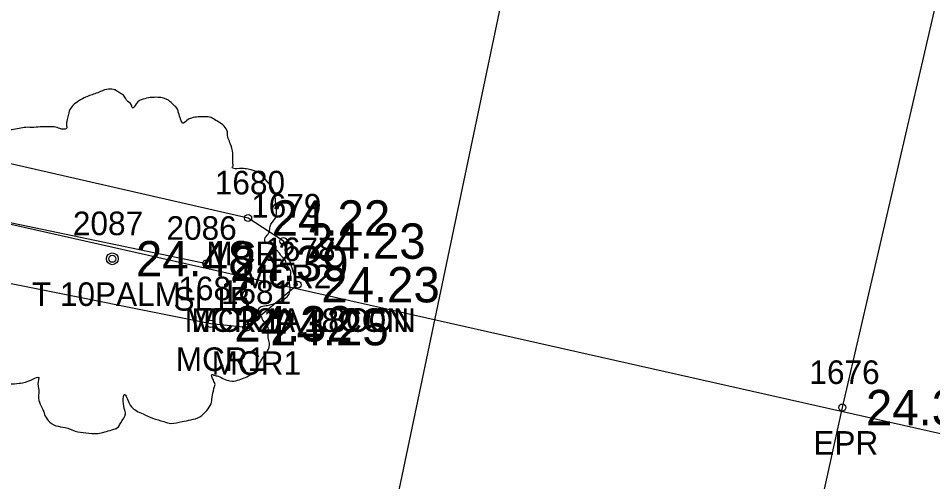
# Model space of a CAD drawing. Extents: x 2654414 to 2656963, y 761776 to 764965.
# Drawn here: x 2655431.68 to 2655470.4, y 762194.36 to 762214.01 of the extents above; entities that cross this region are included whole.
import ezdxf

# ---------------------------------------------------------------- set-up
doc = ezdxf.new("R2010")
doc.units = 0
for name, color, linetype in [('RD_EX_Conc', 7, 'Continuous'), ('RD_EX_Conc_txCode', 7, 'Continuous'), ('RD_EX_DR_Pipe', 7, 'Continuous'), ('RD_EX_Road', 7, 'Continuous'), ('RD_EX_Road_txCode', 7, 'Continuous'), ('RD_EX_TX_Conc_ELEV', 7, 'Continuous'), ('RD_EX_TX_Road_ELEV', 7, 'Continuous'), ('RD_EX_TX_VEG_ELEV', 7, 'Continuous'), ('RD_EX_VEG', 7, 'Continuous'), ('RD_EX_VEG_txCode', 7, 'Continuous'), ('RD_HC_Cl', 7, 'Continuous'), ('RD_SMD_Locator', 7, 'Continuous')]:
    doc.layers.add(name, color=color, linetype=linetype)

msp = doc.modelspace()

# ---------------------------------------------------------------- linework, layer by layer
at = {"layer": 'RD_EX_Conc'}
for points in [[(2655443.509, 762202.713), (2655441.344, 762200.892), (2655439.828, 762201.054), (2655414.24, 762206.177), (2655412.261, 762207.947), (2655412.231, 762209.572), (2655413.306, 762211.312), (2655415.917, 762211.372)], [(2655443.509, 762202.713), (2655442.909, 762204.561), (2655441.41, 762205.54), (2655415.917, 762211.372)]]:
    msp.add_lwpolyline(points, dxfattribs=at)
at = {"layer": 'RD_EX_DR_Pipe'}
msp.add_line((2655454.649, 762226.686), (2655442.695, 762169.731), dxfattribs=at)
at = {"layer": 'RD_EX_Road'}
msp.add_lwpolyline([(2655700.994, 763232.279), (2655693.552, 763198.573), (2655671.649, 763102.037), (2655649.038, 763001.061), (2655627.271, 762906.233), (2655604.996, 762809.365), (2655598.992, 762783.09), (2655583.655, 762714.137), (2655561.97, 762618.323), (2655556.356, 762593.843), (2655548.114, 762557.141), (2655540.102, 762522.478), (2655518.03, 762425.04), (2655496.479, 762329.558), (2655475.552, 762236.625), (2655473.199, 762226.142), (2655466.574, 762197.504), (2655460.058, 762168.164), (2655454.261, 762143.776), (2655432.5, 762049.878), (2655410.7, 761955.515), (2655388.166, 761858.426), (2655373.501, 761793.951)], dxfattribs=at)
at = {"layer": 'RD_EX_VEG'}
msp.add_line((2655415.141, 762208.748), (2655439.646, 762203.615), dxfattribs=at)
for centre, radius in [((2655435.66, 762203.812), 0.25), ((2655435.647, 762203.793), 0.0001)]:
    msp.add_circle(centre, radius, dxfattribs=at)
for points in [[(2655435.792, 762210.979), (2655435.492, 762211.004), (2655435.167, 762210.904), (2655434.917, 762210.804), (2655434.692, 762210.729), (2655434.468, 762210.629), (2655434.168, 762210.454), (2655433.943, 762210.254), (2655433.818, 762210.004), (2655433.768, 762209.779), (2655433.718, 762209.505), (2655433.718, 762209.33), (2655433.593, 762209.305), (2655433.443, 762209.33), (2655433.193, 762209.405), (2655432.943, 762209.405), (2655432.693, 762209.405), (2655432.343, 762209.38), (2655431.994, 762209.38), (2655431.719, 762209.33), (2655431.394, 762209.28), (2655431.019, 762209.155), (2655430.669, 762209.03), (2655430.369, 762208.78), (2655430.119, 762208.305), (2655429.994, 762207.955), (2655429.845, 762207.705), (2655429.994, 762207.256), (2655430.169, 762206.906), (2655430.194, 762206.706), (2655430.269, 762206.281), (2655430.369, 762206.056), (2655430.494, 762205.856), (2655430.419, 762205.831), (2655430.044, 762205.781), (2655429.745, 762205.681), (2655429.32, 762205.456), (2655429.095, 762205.231), (2655428.995, 762204.907), (2655428.97, 762204.557), (2655428.87, 762204.357), (2655428.795, 762204.082), (2655428.77, 762204.007), (2655428.72, 762203.682), (2655428.82, 762203.232), (2655428.845, 762202.882), (2655428.97, 762202.658), (2655429.12, 762202.483), (2655429.295, 762202.233), (2655429.695, 762202.008), (2655430.019, 762201.908), (2655430.219, 762201.883), (2655430.044, 762201.383), (2655429.994, 762201.033), (2655429.87, 762200.633), (2655429.87, 762200.559), (2655429.82, 762200.084), (2655429.969, 762199.759), (2655430.044, 762199.384), (2655430.219, 762199.159), (2655430.494, 762198.859), (2655430.819, 762198.634), (2655431.319, 762198.509), (2655431.719, 762198.534), (2655432.294, 762198.709), (2655432.543, 762198.784), (2655432.518, 762198.609), (2655432.543, 762198.234), (2655432.543, 762197.81), (2655432.693, 762197.485), (2655432.793, 762197.21), (2655432.943, 762196.96), (2655433.268, 762196.735), (2655433.668, 762196.66), (2655434.093, 762196.51), (2655434.543, 762196.435), (2655435.042, 762196.41), (2655435.642, 762196.56), (2655435.917, 762196.685), (2655436.017, 762196.86), (2655436.217, 762197.235), (2655436.167, 762197.46), (2655436.192, 762198.06), (2655436.292, 762197.885), (2655436.467, 762197.535), (2655436.966, 762197.235), (2655437.366, 762197.06), (2655437.841, 762196.91), (2655438.141, 762196.835), (2655438.616, 762196.91), (2655438.991, 762196.985), (2655439.365, 762197.11), (2655439.665, 762197.385), (2655439.84, 762197.66), (2655439.89, 762197.935), (2655439.965, 762198.309), (2655440.015, 762198.484)], [(2655440.015, 762198.484), (2655439.94, 762198.659), (2655439.89, 762198.909), (2655439.965, 762198.884), (2655440.14, 762198.834), (2655440.415, 762198.709), (2655440.64, 762198.634), (2655440.965, 762198.659), (2655441.24, 762198.759), (2655441.689, 762199.034), (2655441.964, 762199.509), (2655442.239, 762199.909), (2655442.314, 762200.234), (2655442.264, 762200.459), (2655442.239, 762200.958), (2655442.039, 762201.208), (2655441.989, 762201.333), (2655441.889, 762201.733), (2655441.964, 762201.783), (2655442.239, 762201.833), (2655442.614, 762201.958), (2655442.889, 762202.083), (2655443.114, 762202.258), (2655443.189, 762202.483), (2655443.164, 762202.882), (2655443.214, 762203.282), (2655443.139, 762203.432), (2655443.039, 762203.582), (2655442.964, 762203.782), (2655442.814, 762203.932), (2655442.714, 762204.082), (2655442.614, 762204.182), (2655442.489, 762204.332), (2655442.314, 762204.457), (2655442.164, 762204.507), (2655442.114, 762204.657), (2655442.264, 762204.857), (2655442.314, 762204.957), (2655442.339, 762205.181), (2655442.564, 762205.531), (2655442.614, 762205.931), (2655442.564, 762206.356), (2655442.514, 762206.631), (2655442.364, 762206.906), (2655442.164, 762207.156), (2655442.039, 762207.331), (2655441.864, 762207.455), (2655441.539, 762207.58), (2655441.29, 762207.63), (2655440.94, 762207.63), (2655440.74, 762207.68), (2655440.765, 762207.73), (2655440.765, 762207.88), (2655440.765, 762208.155), (2655440.69, 762208.605), (2655440.54, 762209.105), (2655440.54, 762209.13), (2655440.44, 762209.38), (2655440.215, 762209.58), (2655440.04, 762209.679), (2655439.84, 762209.804), (2655439.59, 762209.829), (2655439.29, 762209.829), (2655439.016, 762209.779), (2655438.816, 762209.679), (2655438.641, 762209.555), (2655438.566, 762209.704), (2655438.466, 762210.004), (2655438.416, 762210.154), (2655438.266, 762210.329), (2655438.041, 762210.529), (2655437.591, 762210.654), (2655436.966, 762210.579), (2655436.667, 762210.379), (2655436.517, 762210.204), (2655436.467, 762210.329), (2655436.267, 762210.529), (2655436.167, 762210.704), (2655435.992, 762210.829), (2655435.842, 762210.929), (2655435.742, 762210.979)]]:
    msp.add_spline(points, degree=3, dxfattribs=at)
at = {"layer": 'RD_HC_Cl'}
msp.add_line((2655476.255, 762195.138), (2655321.054, 762230.163), dxfattribs=at)
at = {"layer": 'RD_SMD_Locator'}
for centre in [(2655441.41, 762205.54), (2655442.909, 762204.561), (2655435.66, 762203.812), (2655439.646, 762203.615), (2655443.509, 762202.713), (2655443.509, 762202.713), (2655439.828, 762201.054), (2655441.344, 762200.892), (2655466.574, 762197.504)]:
    msp.add_circle(centre, 0.15, dxfattribs=at)

# ---------------------------------------------------------------- texts
at = {"layer": 'RD_EX_Conc_txCode'}
for s, p in [('1680', (2655440.001, 762206.54)), ('1679', (2655441.539, 762205.561)), ('1677', (2655442.139, 762203.713)), ('1678', (2655442.139, 762203.713)), ('MCR2', (2655439.646, 762203.54)), ('MCR2', (2655441.145, 762202.561)), ('1682', (2655438.458, 762202.054)), ('1681', (2655440.257, 762201.892)), ('MCR2A 18CON', (2655438.721, 762200.713)), ('MCR1A 18CON', (2655439.005, 762200.713)), ('MCR1', (2655438.348, 762199.054)), ('MCR1', (2655439.864, 762198.892))]:
    msp.add_text(s, height=1, dxfattribs=at).set_placement(p)
at = {"layer": 'RD_EX_Road_txCode'}
for s, p in [('1676', (2655465.181, 762198.504)), ('EPR', (2655465.346, 762195.504))]:
    msp.add_text(s, height=1, dxfattribs=at).set_placement(p)
at = {"layer": 'RD_EX_TX_Conc_ELEV'}
for s, p in [('24.22', (2655442.41, 762204.79)), ('24.23', (2655443.909, 762203.811)), ('24.23', (2655444.509, 762201.963)), ('24.23', (2655444.509, 762201.963)), ('24.32', (2655440.828, 762200.304)), ('24.25', (2655442.344, 762200.142))]:
    msp.add_text(s, height=1.5, dxfattribs=at).set_placement(p)
at = {"layer": 'RD_EX_TX_Road_ELEV'}
msp.add_text('24.33', height=1.5, dxfattribs=at).set_placement((2655467.574, 762196.754))
at = {"layer": 'RD_EX_TX_VEG_ELEV'}
for s, p in [('24.48', (2655436.66, 762203.062)), ('24.39', (2655440.646, 762202.865))]:
    msp.add_text(s, height=1.5, dxfattribs=at).set_placement(p)
at = {"layer": 'RD_EX_VEG_txCode'}
for s, p in [('2087', (2655433.991, 762204.812)), ('2086', (2655437.953, 762204.615)), ('T 10PALM', (2655432.251, 762201.812)), ('SL1B', (2655438.253, 762201.615))]:
    msp.add_text(s, height=1, dxfattribs=at).set_placement(p)

doc.saveas('drawing.dxf')
